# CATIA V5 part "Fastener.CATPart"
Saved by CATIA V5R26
Part number: Fastener
Bounding box of the stored display mesh (mm): x -4.826 to 4.826, y -4.826 to 4.826, z -47.752 to 0
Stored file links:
  D:\_Deepak\CATIA\CATIA V5 2015 Parts Files\EXE Files\Exercises\c13_catia_v5_6r2015_exr\C13Exr01_cat_v5-6r2015\Fastener_cat_v5-6r2015.CATPart
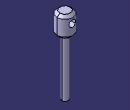
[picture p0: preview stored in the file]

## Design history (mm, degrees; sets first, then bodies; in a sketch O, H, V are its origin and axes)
Body1 (main body)
  Sketch1 on xy-plane, origin (0, 0, 0), H (1, 0, 0), V (0, 1, 0)
    circle A1 centre (0, 0) radius 4.826
    circle A2 centre (0, 0) radius 1.905
    radius A2 = 1.905
    radius A1 = 4.826
  MultiPad1: profile Sketch1, domains (length 0 / length 47.752; length 0 / length 12.7)
  Chamfer1: length 1.5875, angle 45, on 2 edges
  Chamfer2: length 0.508, angle 45, on 1 edge
  Sketch2 on zx-plane, origin (-1.612, 0, 1.612), H (1, 0, 0), V (0, 0, -1)
    point P1 (1.612, 6.35)
    reference intersected line E1 through (1.612, 0) direction (0, 1) from yz-plane
    distance P1 H = 6.35
    coincidence: E1 P1
  Hole1: placed by Sketch2, at (0, 0, -4.738) direction (0, -1, 0), diameter 4.064, depth 10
